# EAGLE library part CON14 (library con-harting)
CONNECTOR
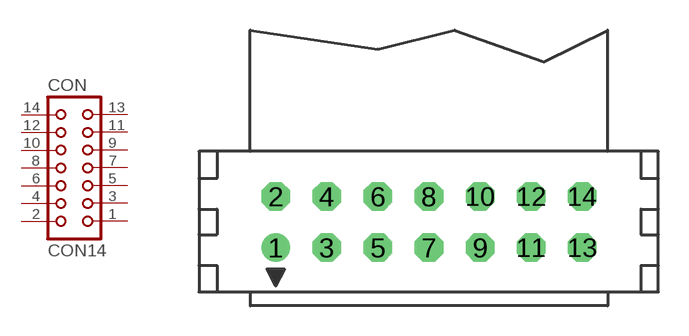
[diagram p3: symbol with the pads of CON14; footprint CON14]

Designator prefix CON

## CON14 (OC_FARNELL: unknown; OC_NEWARK: unknown)  [CON14]
1  1  pas
2  2  pas
3  3  pas
4  4  pas
5  5  pas
6  6  pas
7  7  pas
8  8  pas
9  9  pas
10  10  pas
11  11  pas
12  12  pas
13  13  pas
14  14  pas

## Footprint CON14 (pad centres in mm)
CONNECTOR
drill 0.914 round: 1 -7.62,-1.27
drill 0.914 octagon: 2 -7.62,1.27; 3 -5.08,-1.27; 4 -5.08,1.27; 5 -2.54,-1.27; 6 -2.54,1.27; 7 0,-1.27; 8 0,1.27; 9 2.54,-1.27; 10 2.54,1.27; 11 5.08,-1.27; 12 5.08,1.27; 13 7.62,-1.27; 14 7.62,1.27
